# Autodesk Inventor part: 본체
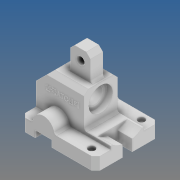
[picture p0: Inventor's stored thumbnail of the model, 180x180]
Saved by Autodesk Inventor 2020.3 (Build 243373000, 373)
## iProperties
Created: 2022-08
Part Number: 본체
Material: 알루미늄 6061
Document SubType Name: Modeling
Designer: EZDESIGN
Density: 2.7 g/cm^3
Appearance: 기본값
Author: EZDESIGN
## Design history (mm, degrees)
sketch "스케치1"
  geometry: L1 (45, -38)-(-45, -38); L2 (-45, -38)-(-45, 38); L3 (-45, 38)-(45, 38); L4 (45, 38)-(45, -38); L5 (45, -38)-(-45, 38); L6 (-45, -38)-(45, 38); 1 further point
  constraints: 12 end point, 2 midpoint, 2 parallel, 1 horizontal, 1 perpendicular
  dimensions: "d0" = 90 distance of L2.end L3.end; "d1" = 76 distance of L1.end L2.end
extrude "돌출1" new body sketch "스케치1" distance "d2" = 15; taper "d3" = 0 deg
sketch "스케치2"
  geometry: L1 (0, 0)-(90, 0) reference; L2 (0, 0)-(0, -15) reference; L3 (90, -15)-(0, -15) reference; L4 (90, 0)-(90, -15) reference; L5 (17, -15)-(17, -7); L6 (17, -7)-(37, -7); L7 (37, -7)-(37, -15); 3 further points
  constraints: 6 end point, 3 point on line, 2 perpendicular, 1 midpoint, 1 vertical, 1 vertical alignment
  dimensions: "d4" = 8 distance of L5.start L5.end; "d5" = 20 distance of L5.end L6.end; "d6" = 27 distance from line of L2 point (27, -15); "d7" = 15 distance of L1.start L2.end (derived)
extrude "돌출2" cut sketch "스케치2" extent not by distance; stored distance "d8" = 0; taper "d9" = 0 deg
sketch "스케치3"
  geometry: L1 (-45, -38)-(45, -38) reference; L2 (45, -38)-(45, 38) reference; L3 (45, 38)-(-45, 38) reference; L4 (-45, 38)-(-45, -38) reference; L5 (13, 20)-(-45, 20); L6 (-45, 20)-(-45, -20); L7 (-45, -20)-(13, -20); L8 (13, -20)-(13, 20); 3 further points
  constraints: 8 end point, 2 parallel, 1 horizontal, 1 horizontal alignment, 1 midpoint, 1 perpendicular, 1 point on line
  dimensions: "d10" = 40 distance between parallel lines of L7 L5; "d11" = 32 distance between parallel lines of L2 L8
extrude "돌출3" join sketch "스케치3" distance "d12" = 45; taper "d13" = 0 deg
sketch "스케치4"
  geometry: L1 (58, 0)-(0, 0) reference; L2 (58, 0)-(58, 45) reference; L3 (0, 45)-(58, 45) reference; L4 (0, 0)-(0, 45) reference; L5 (18, 45)-(0, 27); L6 (18, 45)-(0, 45); L7 (0, 27)-(0, 45); 1 further point
  constraints: 6 end point, 2 collinear, 2 point on line
  dimensions: "d14" = 18 distance of L3.start L5.start; "d15" = 45 deg angle of L3 L5
extrude "돌출4" cut sketch "스케치4" extent not by distance; stored distance "d16" = 18; taper "d17" = 0 deg
sketch "스케치5"
  geometry: L1 (-27, 20)-(-27, -20) reference; L2 (-27, -20)-(13, -20) reference; L3 (13, -20)-(13, 20) reference; L4 (13, 20)-(-27, 20) reference; L5 (-16, 7.5)-(8, 7.5); L6 (8, 7.5)-(8, -7.5); L7 (8, -7.5)-(-16, -7.5); L8 (-16, -7.5)-(-16, 7.5); 2 further points
  constraints: 8 end point, 2 parallel, 1 horizontal, 1 horizontal alignment, 1 midpoint, 1 perpendicular
  dimensions: "d18" = 24 distance of L6.end L7.end; "d19" = 15 distance of L5.end L6.end; "d20" = 5 distance between parallel lines of L3 L6
extrude "돌출5" join sketch "스케치5" distance "d21" = 30; taper "d22" = 0 deg
chamfer "모따기1" distance "d23" = 5; stored, may be unused: second distance "d24" = 2, angle "d25" = 45 deg
sketch "스케치6"
  geometry: L1 (17, -15)-(17, -7) reference; L2 (17, -7)-(37, -7) reference; L3 (37, -7)-(37, -15) reference; L4 (90, -15)-(37, -15) reference; L5 (90, 0)-(90, -15) reference; L6 (0, 0)-(90, 0) reference; L7 (0, 0)-(0, -15) reference; L8 (17, -15)-(0, -15) reference; C1 r 13 at (27, 0); 3 further points
  constraints: 1 centre point, 1 point on line
  dimensions: "d26" = 26 diameter of C1
extrude "돌출6" join sketch "스케치6" stored distance "d27" = 10; taper "d28" = 0 deg
chamfer "모따기2" distance "d29" = 5; stored, may be unused: second distance "d30" = 2, angle "d31" = 45 deg
sketch "스케치7"
  geometry: L1 (45, -33)-(45, 33) reference; L2 (40, 38)-(-5, 38) reference; 3 further points
  dimensions: "d32" = 60 distance of point (32, -30) point (32, 30); "d33" = 13 distance from line of L1 point (32, -30); "d34" = 13 distance from line of L1 point (32, 30); "d35" = 8 distance from line of L2 point (32, 30)
sketch "스케치8"
  geometry: L1 (22.43, 27)-(-50.798, 27); L2 (40, -15)-(-8, -15) reference; L3 (13, 0)-(-5, 0) reference; L4 (13, 0)-(13, 45) reference; L5 (-27, 45)-(13, 45) reference; L6 (-27, 45)-(-45, 27) reference; L7 (-45, 0)-(-45, 27) reference; L8 (-31, 0)-(-45, 0) reference; L9 (13, 27)-(13, 41.5); L10 (13, 41.5)-(6, 41.5); L11 (6, 41.5)-(6, 37); L12 (6, 37)-(-45, 37); L13 (-45, 37)-(-45, 27); L14 (13, 27)-(-45, 27); A1 r 13 centre (-18, 0) between (-5, 0) and (-31, 0) reference; 2 further points
  constraints: 14 end point, 3 perpendicular, 3 point on line, 2 horizontal
  dimensions: "d36" = 42 distance between parallel lines of L2 L1; "d37" = 7 distance of L9.end L10.end; "d38" = 29 diameter of L10 L1; "d39" = 20 diameter of L12 L1
revolve "회전1" sketch "스케치8" stored, may be unused: angle "d40" = 90 deg
sketch "스케치9"
  geometry: L1 (45, -6)-(13, -6); L2 (13, -6)-(13, 6); L3 (13, 6)-(45, 6); L4 (45, 6)-(45, -6); L5 (45, -33)-(45, 33) reference; L6 (13, -20)-(13, 20) reference; L7 (-16, -7.5)-(-16, 7.5) reference; L8 (-16, 7.5)-(8, 7.5) reference; L9 (8, 7.5)-(8, -7.5) reference; L10 (8, -7.5)-(-16, -7.5) reference; L11 (-27, 20)-(-27, -20) reference; L12 (-27, -20)-(13, -20) reference; L13 (13, -20)-(13, 20) reference; L14 (13, 20)-(-27, 20) reference; L15 (13, -20)-(45, -20); L16 (45, -20)-(45, 20); L17 (45, 20)-(13, 20); L18 (13, 20)-(13, -20); L19 (27, -20)-(27, 20); 13 further points
  constraints: 18 end point, 5 midpoint, 4 parallel, 3 perpendicular, 3 point on line, 2 horizontal, 1 coincident
  dimensions: "d41" = 12 distance of L1.end L2.end; "d44" = 18 distance between parallel lines of L16 L19
  node "투영된 루프7"
extrude "돌출7" join sketch "스케치9" distance "d42" = 4; taper "d43" = 0 deg
extrude "돌출8" cut sketch "스케치9" extent not by distance; stored distance "d45" = 75; taper "d46" = 0 deg
sketch "스케치10"
  geometry: L1 (-40, 4)-(0, 4) reference; L2 (0, 4)-(0, 45) reference; L3 (-40, 45)-(0, 45) reference; L4 (-40, 4)-(-40, 45) reference; L5 (-14, 4)-(-14, -15) reference; L6 (13, -15)-(-14, -15) reference; L7 (13, 0)-(13, -15) reference; L8 (0, 0)-(13, 0) reference; L9 (0, 0)-(0, 4) reference; L10 (-14, 4)-(0, 4) reference; L11 (-26, -15)-(-26, 4) reference; L12 (-40, 4)-(-26, 4) reference; L13 (-40, 0)-(-40, 4) reference; L14 (-53, 0)-(-40, 0) reference; L15 (-53, -15)-(-53, 0) reference; L16 (-26, -15)-(-53, -15) reference; C1 r 14.5 at (-20, 27) reference; C2 r 29 at (-20, 27); 1 further point
  constraints: 1 centre point, 1 coincident
  dimensions: "d47" = 58 diameter of C2
extrude "돌출9" cut sketch "스케치10" distance "d48" = 18; taper "d49" = 0 deg
sketch "스케치11"
  geometry: L1 (19, 30)-(24, 25) reference; L2 (5, 30)-(19, 30) reference; L3 (0, 25)-(5, 30) reference; L4 (0, 0)-(0, 25) reference; L5 (24, 0)-(0, 0) reference; L6 (24, 0)-(24, 25) reference; 2 further points
  dimensions: "d78" = 17 distance from line of L5 point (12, 17)
hole "구멍1" sketch "스케치11" at (12, 17) diameter "d50" = 8; stored, may be unused: countersink angle "d54" = 90 deg, drill point angle "d56" = 118 deg; dims "d51" = 6, "d52" = 4, "d53" = 2, "d55" = 8
chamfer "모따기3" distance "d57" = 1; stored, may be unused: second distance "d58" = 2, angle "d59" = 45 deg
chamfer "모따기4" distance "d60" = 1; stored, may be unused: second distance "d61" = 2, angle "d62" = 45 deg
fillet "모깎기1" dims "d63" = 3
hole "구멍2" sketch "스케치7" diameter "d64" = 4.5; stored, may be unused: countersink angle "d68" = 90 deg, drill point angle "d70" = 118 deg; dims "d65" = 6, "d66" = 8, "d67" = 4.4, "d69" = 8
sketch "스케치12"
  geometry: L1 (-6.739, -15.212)-(34.739, -15.212); L2 (34.739, -15.212)-(34.739, -20.788); L3 (34.739, -20.788)-(-6.739, -20.788); L4 (-6.739, -20.788)-(-6.739, -15.212); L5 (0, 0)-(40, 0) reference; L6 (40, -38)-(40, 0) reference; 4 further points
  constraints: 2 midpoint, 1 horizontal alignment, 1 vertical alignment, 2 other
  dimensions: "d71" = 18 distance from line of L5 point (14, -18); "d72" = 26 distance from line of L6 point (14, -18)
feature "엠보싱1" sketch "스케치12" dims "d0" = 90, "d1" = 76, "d73" = 0.5, "d74" = 0
chamfer "모따기5" distance "d75" = 5; stored, may be unused: second distance "d76" = 2, angle "d77" = 45 deg
node "솔리드1"
node "투영된 루프1"
node "투영된 루프2"
node "투영된 루프3"
node "투영된 루프4"
node "투영된 루프5"
node "투영된 루프6"
node "투영된 루프8"
node "투영된 루프9"
node "투영된 루프10"
node "투영된 루프11"
feature "A9D066F2-1C7D-4E18-AEED-F7BC21143FA4" dims "d64" = 4.5, "d65" = 6, "d66" = 8, "d67" = 4.4, "d68" = 90 deg, "d69" = 8, "d70" = 118 deg
